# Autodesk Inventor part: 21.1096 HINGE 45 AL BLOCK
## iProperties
Created: 2007-01
Part Number: 21.1096 HINGE 45 AL BLOCK
Document SubType Name: Modeling
Designer: Andy Moles
Material: Aluminum-6061
Mass: 40.405 g
Surface Area: 63.4284 cm^2
Volume: 14.9096 cm^3
Density: 2.71 g/cm^3
Author: Andy Moles
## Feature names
1. Extrusion1
2. Hole1
3. Hole2
